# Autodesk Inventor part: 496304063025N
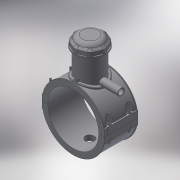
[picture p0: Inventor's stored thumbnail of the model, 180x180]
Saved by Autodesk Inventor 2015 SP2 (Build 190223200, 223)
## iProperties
Created: 2017-07
Part Number: 496304063025N
Material: Generic
Description: PLASSON TAPPING SADDLE 63x25
Document SubType Name: Modeling
Designer: KIM
Mass: 272.099 g
Surface Area: 936.685 cm^2
Volume: 272.099 cm^3
Density: 1 g/cm^3
Appearance: Default
Author: KIM
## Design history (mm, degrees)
derived "496304.ipt"
feature "Solid1::496304.ipt"
feature "Solid2::496304.ipt"
feature "Solid4::496304.ipt"
feature "Solid5::496304.ipt"
tag "TaggingFeature1"
body "Solid1"
body "Solid2"
other parameters: "d0" = 63, "d3" = 15.75, "d4" = 118, "d5" = 0, "d6" = 0.1, "d8" = 0, "d19" = 6, "d20" = 6, "d21" = 70.8, "d23" = 0, "d24" = 35.4, "d26" = 0, "d29" = 3, "d30" = 21, "d31" = 6, "d32" = 0, "d33" = 0, "d34" = 0.6, "d40" = 42.588, "d41" = 56.7, "d43" = 0, "d45" = 0, "d47" = 111.75, "d70" = 15, "d72" = 0, "d73" = 6, "d75" = 5, "d76" = 0, "d77" = 3.15, "d78" = 61.5, "d79" = 15, "d80" = 47.2, "d82" = 5 deg, "d84" = 4, "d85" = 14, "d86" = 0, "d87" = 3, "d88" = 0, "d89" = 1, "d90" = 1, "d91" = 94.4, "d92" = 0, "d93" = 0.5, "d94" = 33.15789, "d96" = 83.538, "d97" = 2.36, "d98" = 0, "d102" = 0.63, "d120" = 140 deg, "d121" = 24.228, "d122" = 20 deg, "d123" = 163.8, "d124" = 49.14, "d126" = 0, "d143" = 64.89, "d145" = 14.53846, "d149" = 0.945, "d150" = 15.99231, "d153" = 118, "d154" = 0, "d156" = 40.95, "d157" = 160 deg, "d159" = 3.78, "d161" = 0.945, "d162" = 70.8, "d163" = 0, "d164" = 31.5, "d167" = 6.3, "d168" = 39.95122, "d170" = 3.375, "d172" = 0, "d173" = 1, "d175" = 31.5, "d176" = 20 deg, "d177" = 4.41, "d178" = 18.9, "d180" = 0, "d183" = 7.56, "d184" = 3.528, "d185" = 38.35, "d186" = 38.35, "d187" = 40.95, "d188" = 5.67, "d189" = 4.41, "d190" = 0, "d191" = 61.425, "d193" = 6.3, "d194" = 4.13, "d195" = 90 deg, "d197" = 0, "d199" = 0, "d200" = 9.45, "d202" = 0, "d204" = 53.865, "d205" = 39.69, "d206" = 48.195, "d207" = 67.5, "d208" = 70.2, "d209" = 83.7, "d210" = 48.762, "d211" = 56.7, "d212" = 45.36, "d213" = -0.45, "d216" = 0, "d217" = 6.3, "d218" = 6.3, "d219" = 1.26, "d222" = 63, "d224" = 0, "d230" = 3.78, "d233" = 6, "d237" = 35.4, "d238" = 6.02433, "d240" = 35.4, "d241" = 35.4, "d242" = 35.4, "d243" = 6, "d244" = 35.4, "d245" = 35.4, "d246" = 35.4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
